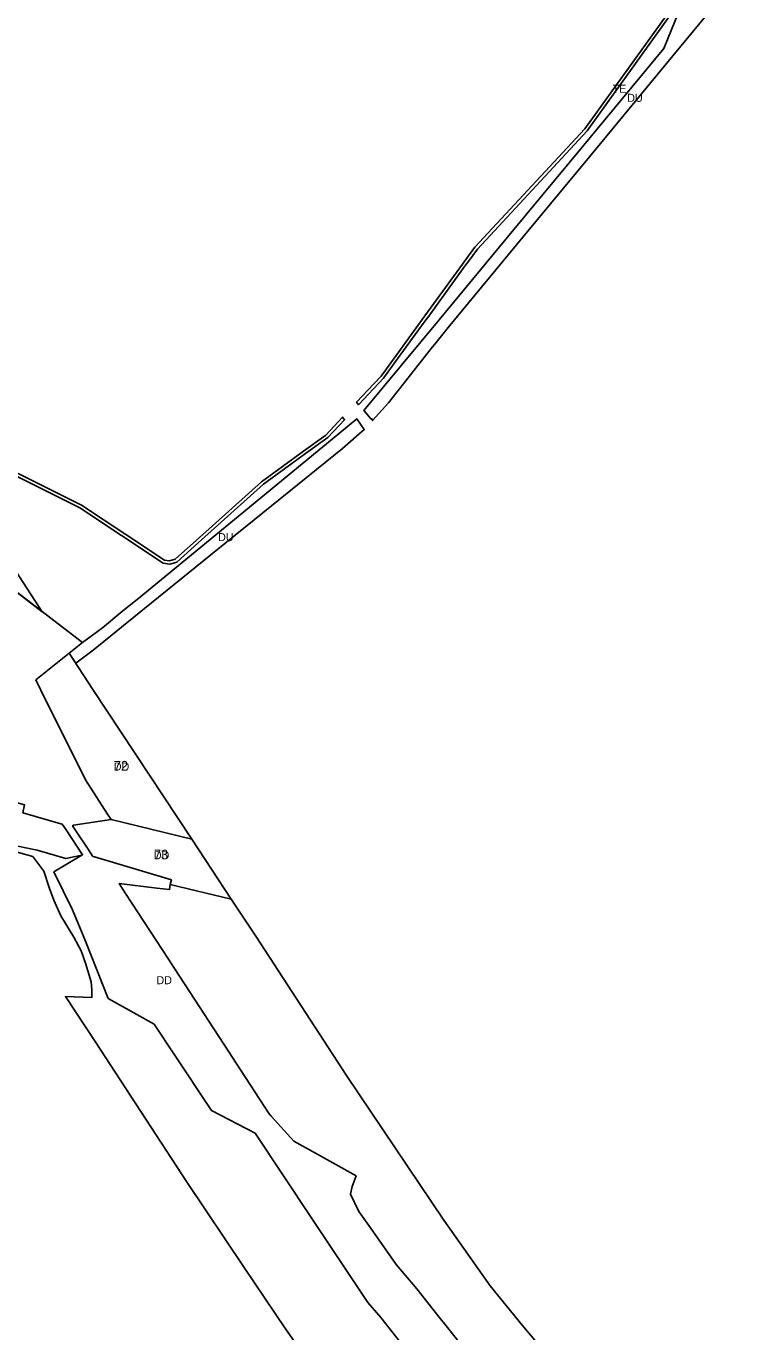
# Model space of a CAD drawing. Extents: x -545758 to -541641, y -1153152 to -1149975.
# Drawn here: x -543644 to -543202, y -1151498 to -1150683 of the extents above; entities that cross this region are included whole.
import ezdxf

# ---------------------------------------------------------------- set-up
doc = ezdxf.new("R2010")
doc.units = 0
for name, color, linetype in [('90310013', 7, 'Continuous'), ('90330013', 7, 'Continuous'), ('90330023', 7, 'Continuous'), ('90400013', 7, 'Continuous'), ('ID_navrh', 7, 'Continuous')]:
    doc.layers.add(name, color=color, linetype=linetype)

msp = doc.modelspace()

# ---------------------------------------------------------------- linework, layer by layer
at = {"layer": '90310013'}
msp.add_lwpolyline([(-543202.13, -1150654.9), (-543240.31, -1150701.11), (-543291.34, -1150762.87), (-543333.86, -1150814.34), (-543380.54, -1150870.84), (-543388.9, -1150881.22), (-543390.27, -1150882.92), (-543417.85, -1150917.85), (-543427.74, -1150929.04), (-543428.35, -1150928.34), (-543427.93, -1150928.2), (-543428.2, -1150927.89), (-543428.63, -1150928.03), (-543433.05, -1150922.99), (-543433.02, -1150922.78), (-543433.14, -1150922.75), (-543386.24, -1150866.12), (-543339.51, -1150809.68), (-543296.93, -1150758.24), (-543245.84, -1150696.55), (-543232.51, -1150663.7)], dxfattribs=at)
msp.add_lwpolyline([(-543570.17, -1151046.52), (-543570.17, -1151046.52), (-543602.19, -1151072.41), (-543613.042, -1151080.7), (-543617.234, -1151074.263), (-543608.97, -1151067.59), (-543596.49, -1151058.45), (-543583.69, -1151048), (-543574.84, -1151040.74), (-543510.38, -1150987.81), (-543445.92, -1150934.89), (-543437.53, -1150927.99), (-543432.98, -1150934.6), (-543446.49, -1150946.51), (-543485.42, -1150977.98), (-543524.34, -1151009.46)], close=True, dxfattribs=at)
at = {"layer": '90330013'}
for points in [[(-543670.14, -1151020.9), (-543608.97, -1151067.59), (-543638.05, -1151091.07), (-543634.9, -1151097.4), (-543607.02, -1151153.49), (-543593.23, -1151174.88), (-543591.06, -1151178.24), (-543614.55, -1151181.8), (-543615.13, -1151182.21), (-543612.66, -1151185.94), (-543605.86, -1151196.19), (-543602.42, -1151201.39), (-543601.53, -1151201.58), (-543553.4, -1151215.92), (-543554.12, -1151218.94), (-543554.5, -1151222.05), (-543562.6, -1151221.1), (-543585.98, -1151218.34), (-543582.01, -1151224.44), (-543555.31, -1151265.47), (-543551.39, -1151271.49), (-543517.62, -1151323.38), (-543512.99, -1151330.5), (-543492.35, -1151362.21), (-543491.12, -1151363.58), (-543477.04, -1151379.29), (-543463.51, -1151386.83), (-543438.04, -1151401.02), (-543440.47, -1151407.63), (-543441.62, -1151412.47), (-543436.29, -1151423.22), (-543430.04, -1151432.08), (-543423.58, -1151441.25), (-543412.96, -1151456.3), (-543400.2, -1151471.61), (-543386.97, -1151488.23), (-543380.16, -1151496.84), (-543358.33, -1151524.47)], [(-543379.7, -1151544.02), (-543422.57, -1151489.55), (-543430.64, -1151480.07), (-543466.03, -1151427.04), (-543501.2, -1151374.23), (-543528.41, -1151360.19), (-543551.48, -1151325.26), (-543564.09, -1151306.26), (-543592.86, -1151290.06), (-543607.08, -1151254.31), (-543615.15, -1151234.83), (-543626.78, -1151211.1), (-543609.43, -1151200.65), (-543608.87, -1151200.33), (-543612.4, -1151194.99), (-543619.19, -1151184.73), (-543621.56, -1151181.15), (-543622.39, -1151180.97), (-543646.12, -1151174.04)]]:
    msp.add_lwpolyline(points, dxfattribs=at)
at = {"layer": '90330023'}
for points in [[(-543650.498, -1151023.182), (-543634.042, -1151048.453), (-543670.14, -1151020.9)], [(-543649.23, -1151194.95), (-543637.18, -1151197.56), (-543619.29, -1151202.61), (-543609.43, -1151200.65), (-543626.78, -1151211.1), (-543615.15, -1151234.83), (-543607.08, -1151254.31), (-543592.86, -1151290.06), (-543564.09, -1151306.26), (-543551.48, -1151325.26), (-543528.41, -1151360.19), (-543501.2, -1151374.23), (-543466.03, -1151427.04), (-543430.64, -1151480.07), (-543422.57, -1151489.55), (-543379.7, -1151544.02)], [(-543450.213, -1151542.021), (-543482.123, -1151496.531), (-543507.895, -1151458.237), (-543544.023, -1151404.554), (-543601.057, -1151317.058), (-543619.594, -1151288.947), (-543603.04, -1151289.47), (-543603.04, -1151284.54), (-543603.6, -1151279.66), (-543606.96, -1151268.13), (-543609.74, -1151260.46), (-543614.45, -1151251.92), (-543622.45, -1151238.56), (-543626.8, -1151228.65), (-543629.48, -1151221.37), (-543633.18, -1151210.51), (-543639.96, -1151201.49), (-543654.84, -1151197.32)], [(-543358.33, -1151524.47), (-543380.16, -1151496.84), (-543386.97, -1151488.23), (-543400.2, -1151471.61), (-543412.96, -1151456.3), (-543423.58, -1151441.25), (-543430.04, -1151432.08), (-543436.29, -1151423.22), (-543441.62, -1151412.47), (-543440.47, -1151407.63), (-543438.04, -1151401.02), (-543463.51, -1151386.83), (-543477.04, -1151379.29), (-543491.12, -1151363.58), (-543492.35, -1151362.21), (-543512.99, -1151330.5), (-543517.62, -1151323.38), (-543551.39, -1151271.49), (-543555.31, -1151265.47), (-543582.01, -1151224.44), (-543585.98, -1151218.34), (-543562.6, -1151221.1), (-543554.5, -1151222.05), (-543554.12, -1151218.94), (-543516.014, -1151228.043), (-543500.703, -1151251.262), (-543443.977, -1151338.286), (-543383.217, -1151428.569), (-543354.407, -1151469.639), (-543334.333, -1151494.346), (-543304.255, -1151530.033)]]:
    msp.add_lwpolyline(points, dxfattribs=at)
for points in [[(-543593.23, -1151174.88), (-543593.23, -1151174.88), (-543607.02, -1151153.49), (-543634.9, -1151097.4), (-543638.05, -1151091.07), (-543617.234, -1151074.263), (-543602.425, -1151097.003), (-543540.715, -1151190.584), (-543591.06, -1151178.24)], [(-543665.68, -1151191), (-543686.982, -1151186.756), (-543699.584, -1151167.645), (-543698.15, -1151163.86), (-543697.39, -1151161.85), (-543691.46, -1151156.42), (-543645.1, -1151169.14), (-543646.12, -1151174.04), (-543622.39, -1151180.97), (-543621.56, -1151181.15), (-543619.19, -1151184.73), (-543612.4, -1151194.99), (-543608.87, -1151200.33), (-543609.43, -1151200.65), (-543619.29, -1151202.61), (-543637.18, -1151197.56), (-543649.23, -1151194.95)], [(-543602.42, -1151201.39), (-543602.42, -1151201.39), (-543605.86, -1151196.19), (-543612.66, -1151185.94), (-543615.13, -1151182.21), (-543614.55, -1151181.8), (-543591.06, -1151178.24), (-543540.715, -1151190.584), (-543516.014, -1151228.043), (-543554.12, -1151218.94), (-543553.4, -1151215.92), (-543601.53, -1151201.58)]]:
    msp.add_lwpolyline(points, close=True, dxfattribs=at)
at = {"layer": '90400013'}
for points in [[(-543235.36, -1150666.74), (-543293.65, -1150747.91), (-543362.29, -1150821.83), (-543368.16, -1150829.86), (-543370.27, -1150832.8), (-543392.737, -1150863.69), (-543395.45, -1150867.42), (-543410.13, -1150887.6), (-543420.96, -1150902.48), (-543436.35, -1150918.98), (-543436.46, -1150919.09), (-543437.78, -1150917.57), (-543427.02, -1150906.04), (-543422.5, -1150901.2), (-543411.47, -1150886.04), (-543396.8, -1150865.87), (-543371.69, -1150831.35), (-543369.49, -1150828.33), (-543363.84, -1150820.56), (-543295.21, -1150746.65), (-543236.92, -1150665.47)], [(-543653.68, -1150959.8), (-543637.45, -1150967.92), (-543609.52, -1150981.9), (-543581.82, -1151000.28), (-543557.76, -1151016.25), (-543554.5, -1151016.74), (-543551.03, -1151015.72), (-543535.83, -1151002.06), (-543497.08, -1150967.22), (-543470.91, -1150948.15), (-543457.05, -1150938.05), (-543446.48, -1150926.86), (-543445.28, -1150928.5), (-543455.73, -1150939.56), (-543469.6, -1150949.67), (-543495.83, -1150968.78), (-543534.52, -1151003.56), (-543550.03, -1151017.5), (-543554.36, -1151018.79), (-543558.5, -1151018.16), (-543610.53, -1150983.63), (-543681.92, -1150947.91)]]:
    msp.add_lwpolyline(points, dxfattribs=at)

# ---------------------------------------------------------------- texts
at = {"layer": '90310013'}
for p in [(-543268.706, -1150729.818), (-543524.267, -1151004.345)]:
    msp.add_text('DU', height=5, rotation=360, dxfattribs=at).set_placement(p)
at = {"layer": '90330013'}
msp.add_text('DD', height=5, rotation=360, dxfattribs=at).set_placement((-543562.725, -1151281.196))
at = {"layer": '90330023'}
for p in [(-543589.383, -1151147.716), (-543564.362, -1151203.141)]:
    msp.add_text('DD', height=5, rotation=360, dxfattribs=at).set_placement(p)
at = {"layer": '90400013'}
msp.add_text('TE', height=5, rotation=360, dxfattribs=at).set_placement((-543277.84, -1150724.177))
at = {"layer": 'ID_navrh'}
msp.add_text('72', height=6, rotation=0, dxfattribs=at).set_placement((-543589.383, -1151147.716))
msp.add_text('73', height=6, dxfattribs=at).set_placement((-543564.362, -1151203.141))

doc.saveas('drawing.dxf')
